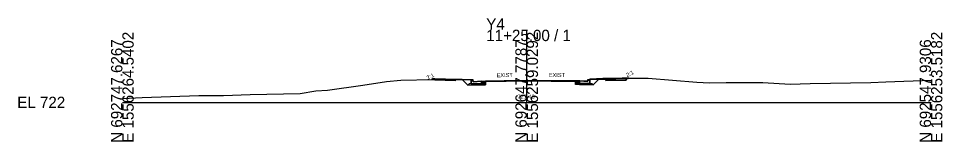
# Model space of a CAD drawing. Extents: x -26 to 203, y -10 to 1521.
# Drawn here: x -25.7 to 202.8, y 1490.3 to 1520.8 of the extents above; entities that cross this region are included whole.
import ezdxf

# ---------------------------------------------------------------- set-up
doc = ezdxf.new("R2010")
doc.units = 0
for name, color, linetype in [('Exist CMT Pavement', 7, 'Continuous'), ('Exist Cross Section Cell', 7, 'Continuous'), ('Exist XS Center Line Elevation Label', 7, 'Continuous'), ('Exist XS Ground Line', 7, 'Continuous'), ('Prop CMT Conc Surface', 7, 'Continuous'), ('Prop CMT Concrete Structures', 7, 'Continuous'), ('Prop CMT Pvmt Course 1', 7, 'Continuous'), ('Prop CMT Pvmt Course 1 CG', 7, 'Continuous'), ('Prop CMT Pvmt Course 2', 7, 'Continuous'), ('Prop CMT Pvmt Course 3', 7, 'Continuous'), ('Prop CMT Pvmt Surface', 7, 'Continuous'), ('Prop CMT Slope Grass', 7, 'Continuous'), ('Prop CMT Subgrade Earthwork', 7, 'Continuous'), ('Prop XS Earthwork Shape', 7, 'Continuous'), ('Prop XS SE Text', 7, 'Continuous'), ('Prop XS Side Slope Text', 7, 'Continuous')]:
    doc.layers.add(name, color=color, linetype=linetype)

msp = doc.modelspace()

# ---------------------------------------------------------------- linework, layer by layer
at = {"layer": 'Exist CMT Pavement'}
for p, q in [((89.78, 1505.25), (94.39, 1505.33)), ((94.39, 1505.33), (100.02, 1505.43)), ((100.02, 1505.43), (100.87, 1505.44)), ((100.87, 1505.44), (106.84, 1505.38)), ((106.84, 1505.38), (112.08, 1505.32))]:
    msp.add_line(p, q, dxfattribs=at)
at = {"layer": 'Exist Cross Section Cell'}
for p, q in [((100, 1500), (100, 1517.98)), ((0, 1500), (100, 1500)), ((100, 1500), (200, 1500))]:
    msp.add_line(p, q, dxfattribs=at)
at = {"layer": 'Exist XS Ground Line'}
msp.add_lwpolyline([(0, 1500.99), (4.93, 1501.2), (18.89, 1501.71), (24.99, 1501.68), (31.6, 1501.92), (43.99, 1502.21), (47.84, 1502.84), (50.74, 1503), (59.44, 1504.23), (65.33, 1505.21), (68.91, 1505.48), (76.72, 1505.69), (77.57, 1505.69), (78.41, 1505.75), (83.01, 1505.64), (86.34, 1505.61), (86.97, 1505.17), (88.75, 1505.23), (100.02, 1505.43), (100.87, 1505.44), (112.81, 1505.31), (113.12, 1505.31), (114.87, 1505.27), (115.59, 1505.72), (118.8, 1505.93), (123.64, 1505.99), (124.22, 1505.99), (130.05, 1505.97), (142.05, 1505), (145.18, 1504.83), (149.32, 1504.96), (158.37, 1504.89), (165.12, 1504.53), (170.08, 1504.64), (185.15, 1504.94), (188.78, 1505.08), (200, 1505.54)], dxfattribs=at)
at = {"layer": 'Prop CMT Conc Surface'}
for points in [[(82.28, 1505.7), (77.28, 1505.8)], [(86.78, 1505.11), (86.77, 1505.61), (86.27, 1505.61)], [(88.78, 1505.23), (86.78, 1505.11)], [(113.08, 1505.31), (115.08, 1505.19)], [(115.08, 1505.19), (115.09, 1505.69), (115.59, 1505.69)], [(119.58, 1505.78), (124.58, 1505.88)]]:
    msp.add_lwpolyline(points, dxfattribs=at)
at = {"layer": 'Prop CMT Concrete Structures'}
for points in [[(77.28, 1505.47), (77.28, 1505.8)], [(77.28, 1505.8), (82.28, 1505.7)], [(82.28, 1505.37), (77.28, 1505.47)], [(82.28, 1505.7), (82.28, 1505.37)], [(88.78, 1505.23), (86.78, 1505.11), (86.77, 1505.61), (86.27, 1505.61)], [(86.27, 1505.61), (86.28, 1504.6), (88.78, 1504.65)], [(88.78, 1504.65), (88.78, 1505.23)], [(113.08, 1505.31), (115.08, 1505.19), (115.09, 1505.69), (115.59, 1505.69)], [(115.59, 1505.69), (115.58, 1504.67), (113.08, 1504.72)], [(113.08, 1504.72), (113.08, 1505.31)], [(124.58, 1505.88), (119.58, 1505.78)], [(119.58, 1505.78), (119.58, 1505.44)], [(119.58, 1505.44), (124.58, 1505.54)], [(124.58, 1505.54), (124.58, 1505.88)]]:
    msp.add_lwpolyline(points, dxfattribs=at)
at = {"layer": 'Prop CMT Pvmt Course 1'}
for p, q in [((89.78, 1505.13), (100, 1505.3)), ((89.78, 1505.13), (89.78, 1505)), ((100, 1505.3), (112.08, 1505.19)), ((112.08, 1505.19), (112.08, 1505.07))]:
    msp.add_line(p, q, dxfattribs=at)
for points in [[(88.78, 1505.23), (88.78, 1504.98)], [(100, 1505.43), (100, 1505.3)], [(100, 1505.43), (113.08, 1505.31)], [(100, 1505.3), (100, 1505.43)], [(113.08, 1505.06), (112.08, 1505.07)], [(113.08, 1505.31), (113.08, 1505.06)]]:
    msp.add_lwpolyline(points, dxfattribs=at)
at = {"layer": 'Prop CMT Pvmt Course 1 CG'}
for points in [[(88.78, 1504.65), (85.78, 1504.59), (85.44, 1504.25)], [(85.44, 1504.25), (88.78, 1504.32)], [(88.78, 1504.4), (88.78, 1504.65)], [(113.08, 1504.72), (116.08, 1504.66), (116.42, 1504.32)], [(113.08, 1504.47), (113.08, 1504.72)], [(116.42, 1504.32), (113.08, 1504.39)]]:
    msp.add_lwpolyline(points, dxfattribs=at)
at = {"layer": 'Prop CMT Pvmt Course 2'}
for p, q in [((88.78, 1504.98), (89.78, 1505)), ((89.78, 1505), (89.78, 1504.67)), ((112.08, 1505.07), (112.08, 1504.73))]:
    msp.add_line(p, q, dxfattribs=at)
for points in [[(88.78, 1504.98), (88.78, 1504.65)], [(112.08, 1505.07), (113.08, 1505.06)], [(113.08, 1504.72), (112.08, 1504.73)], [(113.08, 1505.06), (113.08, 1504.72)]]:
    msp.add_lwpolyline(points, dxfattribs=at)
at = {"layer": 'Prop CMT Pvmt Course 3'}
for p, q in [((88.78, 1504.65), (89.78, 1504.67)), ((89.78, 1504.67), (89.78, 1504.33)), ((112.08, 1504.73), (112.08, 1504.4))]:
    msp.add_line(p, q, dxfattribs=at)
for points in [[(88.78, 1504.65), (88.78, 1504.32)], [(112.08, 1504.73), (113.08, 1504.72)], [(113.08, 1504.72), (113.08, 1504.39)]]:
    msp.add_lwpolyline(points, dxfattribs=at)
at = {"layer": 'Prop CMT Pvmt Surface'}
msp.add_line((88.78, 1505.23), (100, 1505.43), dxfattribs=at)
msp.add_lwpolyline([(100, 1505.43), (113.08, 1505.31)], dxfattribs=at)
at = {"layer": 'Prop CMT Slope Grass'}
for p, q in [((76.54, 1505.69), (76.78, 1505.8)), ((125.3, 1505.99), (125.08, 1505.88))]:
    msp.add_line(p, q, dxfattribs=at)
for points in [[(86.27, 1505.61), (76.78, 1505.8)], [(115.59, 1505.69), (125.08, 1505.88)]]:
    msp.add_lwpolyline(points, dxfattribs=at)
at = {"layer": 'Prop CMT Subgrade Earthwork'}
for p, q in [((88.78, 1504.32), (89.78, 1504.33)), ((89.78, 1504.33), (89.78, 1505.25)), ((112.08, 1504.4), (112.08, 1505.32)), ((113.08, 1504.39), (112.08, 1504.4))]:
    msp.add_line(p, q, dxfattribs=at)
for points in [[(88.78, 1504.32), (85.44, 1504.25), (84.03, 1505.66)], [(113.08, 1504.39), (116.42, 1504.32), (117.83, 1505.73)]]:
    msp.add_lwpolyline(points, dxfattribs=at)
at = {"layer": 'Prop XS Earthwork Shape'}
for points in [[(77.28, 1505.8), (76.78, 1505.8), (76.54, 1505.69), (76.72, 1505.69), (77.28, 1505.69)], [(82.28, 1505.65), (82.28, 1505.37), (77.28, 1505.47), (77.28, 1505.69), (77.57, 1505.69), (78.41, 1505.75)], [(84.06, 1505.63), (84.03, 1505.66), (82.28, 1505.7), (82.28, 1505.65), (83.01, 1505.64)], [(84.06, 1505.63), (86.27, 1505.61), (86.28, 1504.6), (88.78, 1504.65), (88.78, 1505.23), (89.78, 1505.25), (89.78, 1504.33), (88.78, 1504.32), (85.44, 1504.25)], [(86.27, 1505.61), (86.34, 1505.61), (86.77, 1505.31), (86.78, 1505.11), (88.78, 1505.23), (88.78, 1504.65), (86.28, 1504.6)], [(88.78, 1505.23), (86.78, 1505.11), (86.77, 1505.31), (86.97, 1505.17), (88.75, 1505.23)], [(89.78, 1505.25), (100.02, 1505.43), (94.39, 1505.33)], [(100.14, 1505.43), (100.87, 1505.44), (112.08, 1505.32)], [(115.59, 1505.69), (117.83, 1505.73), (116.42, 1504.32), (113.08, 1504.39), (112.08, 1504.4), (112.08, 1505.32), (113.08, 1505.31), (113.08, 1504.72), (115.58, 1504.67)], [(112.08, 1505.32), (113.08, 1505.31), (112.81, 1505.31)], [(115.08, 1505.19), (115.08, 1505.4), (115.54, 1505.69), (115.59, 1505.69), (115.58, 1504.67), (113.08, 1504.72), (113.08, 1505.31)], [(115.08, 1505.19), (115.08, 1505.4), (114.87, 1505.27), (113.12, 1505.31), (113.08, 1505.31)], [(115.59, 1505.69), (117.83, 1505.73), (119.58, 1505.78), (124.58, 1505.88), (125.08, 1505.88), (125.3, 1505.99), (124.22, 1505.99), (123.64, 1505.99), (118.8, 1505.93), (115.59, 1505.72), (115.54, 1505.69)], [(119.58, 1505.78), (124.58, 1505.88), (124.58, 1505.54), (119.58, 1505.44)]]:
    msp.add_lwpolyline(points, close=True, dxfattribs=at)

# ---------------------------------------------------------------- texts
at = {"layer": 'Exist Cross Section Cell'}
for s, p in [('Y4', (90, 1517.98)), ('11+25.00 / 1', (90, 1515.18)), ('EL 722', (-26, 1498.6))]:
    msp.add_text(s, height=2.8, dxfattribs=at).set_placement(p)
for s, p in [('N 692747.6267', (0, 1490)), ('E 1556264.5402', (2.8, 1490)), ('N 692647.7787', (100, 1490)), ('E 1556259.0292', (102.8, 1490)), ('N 692547.9306', (200, 1490)), ('E 1556253.5182', (202.8, 1490))]:
    msp.add_text(s, height=2.8, rotation=90, dxfattribs=at).set_placement(p)
at = {"layer": 'Exist XS Center Line Elevation Label'}
msp.add_text('727.43', height=1, dxfattribs=at).set_placement((97.74, 1500.93))
at = {"layer": 'Prop XS SE Text'}
for rotation, p in [(1.0074, (92.58, 1506.22)), (359.4617, (105.47, 1506.3))]:
    msp.add_text('EXIST', height=1, rotation=rotation, dxfattribs=at).set_placement(p)
at = {"layer": 'Prop XS Side Slope Text'}
for p in [(75.52, 1505.56), (124.88, 1506.23)]:
    msp.add_text('2:1', height=1, rotation=26.5651, dxfattribs=at).set_placement(p)

doc.saveas('drawing.dxf')
